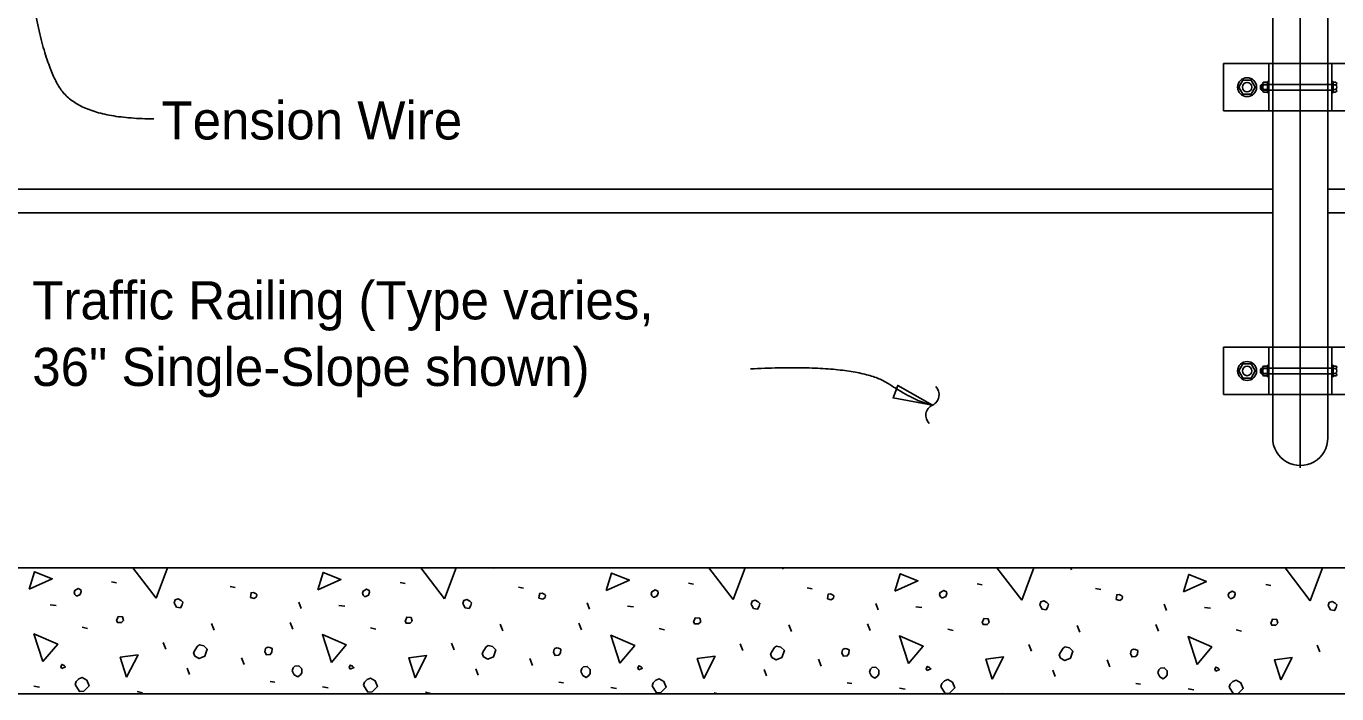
# Model space of a CAD drawing. Extents: x 0 to 41.2, y 0 to 26.
# Drawn here: x 5.48 to 12.4, y 13.47 to 17 of the extents above; entities that cross this region are included whole.
import ezdxf

# ---------------------------------------------------------------- set-up
doc = ezdxf.new("R2010")
doc.units = 0
for name, color, linetype in [('CL_Major', 7, 'Continuous'), ('Dimension', 7, 'Continuous'), ('Miscellaneous', 7, 'Continuous'), ('SteelMisc', 7, 'Continuous'), ('SteelMisc_h', 7, 'Continuous'), ('SupstrConc', 7, 'Continuous'), ('TextStructures', 7, 'Continuous')]:
    doc.layers.add(name, color=color, linetype=linetype)

msp = doc.modelspace()

# ---------------------------------------------------------------- linework, layer by layer
at = {"layer": 'CL_Major'}
msp.add_line((12.2062, 24.6326), (12.2062, 14.6639), dxfattribs=at)
at = {"layer": 'Dimension'}
msp.add_lwpolyline([(10.2634, 14.9952), (10.0798, 15.0997), (10.0556, 15.0334)], close=True, dxfattribs=at)
for centre, start, end in [((10.2392, 15.0503), 294.14658, 45.87379), ((10.2879, 14.9415), 114.14657, 225.87379)]:
    msp.add_arc(centre, 0.0596, start, end, dxfattribs=at)
for points in [[(6.1508, 16.5088), (5.753, 16.5088), (5.549, 16.8458), (5.4877, 17.3027)], [(9.3027, 15.1869), (9.8656, 15.2152), (10.187, 15.0071), (10.2636, 14.9959)]]:
    msp.add_open_spline(points, degree=2, dxfattribs=at)
at = {"layer": 'Miscellaneous'}
for p, q in [((11.9986, 16.6691), (11.9986, 16.6812)), ((12.0044, 16.6691), (12.0044, 16.6812)), ((11.9986, 15.1691), (11.9986, 15.1812)), ((12.0044, 15.1691), (12.0044, 15.1812)), ((7.9504, 14.1326), (7.9491, 14.1361)), ((9.4742, 14.129), (9.4716, 14.1361)), ((10.9981, 14.1255), (10.9942, 14.1361)), ((5.9281, 14.0619), (5.9546, 14.0566)), ((7.4519, 14.0583), (7.4784, 14.053)), ((8.9757, 14.0548), (9.0023, 14.0495)), ((10.4996, 14.0513), (10.5261, 14.046)), ((6.5539, 14.0371), (6.5804, 14.0318)), ((8.0777, 14.0336), (8.1042, 14.0283)), ((9.6015, 14.0301), (9.628, 14.0247)), ((11.1253, 14.0265), (11.1519, 14.0212)), ((12.0234, 14.0477), (12.0499, 14.0424)), ((5.6046, 13.9399), (5.6364, 13.9364)), ((6.9287, 13.9205), (6.9163, 13.954)), ((7.1284, 13.9364), (7.1602, 13.9328)), ((8.4525, 13.9169), (8.4401, 13.9505)), ((8.6522, 13.9328), (8.6841, 13.9293)), ((9.9763, 13.9134), (9.9639, 13.947)), ((10.1761, 13.9293), (10.2079, 13.9258)), ((11.5001, 13.9098), (11.4877, 13.9434)), ((11.6999, 13.9258), (11.7317, 13.9222)), ((6.8862, 13.8108), (6.8721, 13.8462)), ((5.7725, 13.8215), (5.8008, 13.8144)), ((6.4708, 13.8055), (6.4567, 13.8409)), ((7.2964, 13.8179), (7.3246, 13.8108)), ((7.9946, 13.802), (7.9805, 13.8374)), ((8.4101, 13.8073), (8.3959, 13.8427)), ((8.8202, 13.8144), (8.8485, 13.8073)), ((9.5184, 13.7985), (9.5043, 13.8338)), ((9.9339, 13.8038), (9.9197, 13.8391)), ((10.344, 13.8108), (10.3723, 13.8038)), ((11.0423, 13.7949), (11.0281, 13.8303)), ((11.4577, 13.8002), (11.4435, 13.8356)), ((11.8678, 13.8073), (11.8961, 13.8002)), ((6.2145, 13.7048), (6.2003, 13.7401)), ((7.7383, 13.7012), (7.7242, 13.7366)), ((9.2621, 13.6977), (9.248, 13.7331)), ((10.7859, 13.6942), (10.7718, 13.7295)), ((12.3097, 13.6906), (12.2956, 13.726)), ((6.6281, 13.6235), (6.614, 13.6588)), ((8.152, 13.6199), (8.1378, 13.6553)), ((9.6758, 13.6164), (9.6616, 13.6518)), ((11.1996, 13.6129), (11.1854, 13.6482)), ((6.34, 13.5722), (6.3276, 13.6058)), ((7.8638, 13.5687), (7.8514, 13.6023)), ((9.3876, 13.5651), (9.3753, 13.5987)), ((10.9114, 13.5616), (10.8991, 13.5952)), ((5.518, 13.5103), (5.548, 13.505)), ((6.766, 13.5351), (6.7908, 13.5315)), ((7.0418, 13.5068), (7.0719, 13.5015)), ((8.2898, 13.5315), (8.3146, 13.528)), ((8.5656, 13.5033), (8.5957, 13.498)), ((9.8137, 13.528), (9.8384, 13.5245)), ((10.0894, 13.4997), (10.1195, 13.4944)), ((11.3375, 13.5245), (11.3622, 13.5209)), ((6.0625, 13.482), (6.0907, 13.475)), ((7.5863, 13.4785), (7.6146, 13.4714)), ((9.1101, 13.475), (9.1322, 13.4695)), ((10.6339, 13.4714), (10.6418, 13.4695)), ((11.6132, 13.4962), (11.6433, 13.4909))]:
    msp.add_line(p, q, dxfattribs=at)
for points in [[(6.1632, 13.9753), (6.041, 14.1361)], [(6.2233, 14.1361), (6.1632, 13.9753)], [(7.687, 13.9717), (7.5621, 14.1361)], [(7.7485, 14.1361), (7.687, 13.9717)], [(9.2109, 13.9682), (9.0832, 14.1361)], [(9.2736, 14.1361), (9.2109, 13.9682)], [(10.7347, 13.9646), (10.6043, 14.1361)], [(10.7988, 14.1361), (10.7347, 13.9646)], [(12.2585, 13.9611), (12.1255, 14.1361)], [(12.3239, 14.1361), (12.2585, 13.9611)], [(5.4932, 14.023), (5.5215, 14.1149), (5.6152, 14.0778), (5.4932, 14.023)], [(7.0171, 14.0194), (7.0453, 14.1114), (7.139, 14.0742), (7.0171, 14.0194)], [(8.5409, 14.0159), (8.5692, 14.1078), (8.6628, 14.0707), (8.5409, 14.0159)], [(10.0647, 14.0124), (10.093, 14.1043), (10.1867, 14.0672), (10.0647, 14.0124)], [(11.5885, 14.0088), (11.6168, 14.1008), (11.7105, 14.0636), (11.5885, 14.0088)], [(5.7407, 13.9876), (5.7478, 13.9876), (5.7619, 13.9947), (5.7672, 14.0106), (5.7655, 14.0194), (5.7513, 14.0265), (5.7337, 14.0159), (5.7301, 14.0053), (5.7337, 13.9947), (5.7407, 13.9876)], [(6.6617, 13.9788), (6.6812, 13.9735), (6.6935, 13.9823), (6.6953, 13.9947), (6.6918, 13.9982), (6.6776, 14.0053), (6.6653, 14.0035), (6.6635, 13.9912), (6.6617, 13.9788)], [(7.2645, 13.9841), (7.2716, 13.9841), (7.2858, 13.9912), (7.2911, 14.0071), (7.2893, 14.0159), (7.2751, 14.023), (7.2575, 14.0124), (7.2539, 14.0018), (7.2575, 13.9912), (7.2645, 13.9841)], [(8.1855, 13.9753), (8.205, 13.9699), (8.2174, 13.9788), (8.2191, 13.9912), (8.2156, 13.9947), (8.2015, 14.0018), (8.1891, 14), (8.1873, 13.9876), (8.1855, 13.9753)], [(8.7884, 13.9806), (8.7954, 13.9806), (8.8096, 13.9876), (8.8149, 14.0035), (8.8131, 14.0124), (8.799, 14.0194), (8.7813, 14.0088), (8.7777, 13.9982), (8.7813, 13.9876), (8.7884, 13.9806)], [(9.7094, 13.9717), (9.7288, 13.9664), (9.7412, 13.9753), (9.7429, 13.9876), (9.7394, 13.9912), (9.7253, 13.9982), (9.7129, 13.9965), (9.7111, 13.9841), (9.7094, 13.9717)], [(10.3122, 13.977), (10.3192, 13.977), (10.3334, 13.9841), (10.3387, 14), (10.3369, 14.0088), (10.3228, 14.0159), (10.3051, 14.0053), (10.3016, 13.9947), (10.3051, 13.9841), (10.3122, 13.977)], [(11.2332, 13.9682), (11.2526, 13.9629), (11.265, 13.9717), (11.2668, 13.9841), (11.2632, 13.9876), (11.2491, 13.9947), (11.2367, 13.9929), (11.2349, 13.9806), (11.2332, 13.9682)], [(11.836, 13.9735), (11.8431, 13.9735), (11.8572, 13.9806), (11.8625, 13.9965), (11.8607, 14.0053), (11.8466, 14.0124), (11.8289, 14.0018), (11.8254, 13.9912), (11.8289, 13.9806), (11.836, 13.9735)], [(6.2622, 13.9434), (6.2711, 13.9275), (6.2923, 13.924), (6.3011, 13.9399), (6.3046, 13.954), (6.2958, 13.9629), (6.2799, 13.9717), (6.264, 13.9664), (6.2587, 13.9505), (6.2622, 13.9434)], [(7.786, 13.9399), (7.7949, 13.924), (7.8161, 13.9205), (7.8249, 13.9364), (7.8285, 13.9505), (7.8196, 13.9593), (7.8037, 13.9682), (7.7878, 13.9629), (7.7825, 13.947), (7.786, 13.9399)], [(9.3098, 13.9364), (9.3187, 13.9205), (9.3399, 13.9169), (9.3487, 13.9328), (9.3523, 13.947), (9.3434, 13.9558), (9.3275, 13.9646), (9.3116, 13.9593), (9.3063, 13.9434), (9.3098, 13.9364)], [(10.8337, 13.9328), (10.8425, 13.9169), (10.8637, 13.9134), (10.8726, 13.9293), (10.8761, 13.9434), (10.8672, 13.9523), (10.8513, 13.9611), (10.8354, 13.9558), (10.8301, 13.9399), (10.8337, 13.9328)], [(12.3575, 13.9293), (12.3663, 13.9134), (12.3875, 13.9098), (12.3964, 13.9258), (12.3999, 13.9399), (12.3911, 13.9487), (12.3752, 13.9576), (12.3592, 13.9523), (12.3539, 13.9364), (12.3575, 13.9293)], [(5.9599, 13.8462), (5.9811, 13.8462), (5.9917, 13.8568), (5.9864, 13.8763), (5.9635, 13.878), (5.9599, 13.8674), (5.9546, 13.8586), (5.9599, 13.8462), (5.9564, 13.8497)], [(7.4837, 13.8427), (7.505, 13.8427), (7.5156, 13.8533), (7.5103, 13.8727), (7.4873, 13.8745), (7.4837, 13.8639), (7.4784, 13.855), (7.4837, 13.8427), (7.4802, 13.8462)], [(9.0076, 13.8391), (9.0288, 13.8391), (9.0394, 13.8497), (9.0341, 13.8692), (9.0111, 13.871), (9.0076, 13.8603), (9.0023, 13.8515), (9.0076, 13.8391), (9.004, 13.8427)], [(10.5314, 13.8356), (10.5526, 13.8356), (10.5632, 13.8462), (10.5579, 13.8657), (10.5349, 13.8674), (10.5314, 13.8568), (10.5261, 13.848), (10.5314, 13.8356), (10.5278, 13.8391)], [(12.0552, 13.8321), (12.0764, 13.8321), (12.087, 13.8427), (12.0817, 13.8621), (12.0587, 13.8639), (12.0552, 13.8533), (12.0499, 13.8444), (12.0552, 13.8321), (12.0517, 13.8356)], [(5.5657, 13.6394), (5.518, 13.7861), (5.6435, 13.7313), (5.5657, 13.6394)], [(7.0895, 13.6358), (7.0418, 13.7826), (7.1673, 13.7278), (7.0895, 13.6358)], [(8.6133, 13.6323), (8.5656, 13.779), (8.6911, 13.7242), (8.6133, 13.6323)], [(10.1372, 13.6288), (10.0894, 13.7755), (10.2149, 13.7207), (10.1372, 13.6288)], [(6.3683, 13.6677), (6.3913, 13.6553), (6.4213, 13.6677), (6.4337, 13.7048), (6.416, 13.7225), (6.393, 13.7278), (6.3824, 13.7207), (6.37, 13.7012), (6.3612, 13.6853), (6.3683, 13.6677)], [(6.7377, 13.6906), (6.7466, 13.6747), (6.766, 13.6765), (6.7749, 13.6889), (6.7766, 13.7083), (6.7643, 13.7136), (6.7554, 13.7154), (6.7448, 13.7119), (6.7413, 13.7083), (6.7377, 13.6906)], [(7.8921, 13.6641), (7.9151, 13.6518), (7.9451, 13.6641), (7.9575, 13.7012), (7.9398, 13.7189), (7.9168, 13.7242), (7.9062, 13.7172), (7.8939, 13.6977), (7.885, 13.6818), (7.8921, 13.6641)], [(8.2616, 13.6871), (8.2704, 13.6712), (8.2898, 13.673), (8.2987, 13.6853), (8.3005, 13.7048), (8.2881, 13.7101), (8.2792, 13.7119), (8.2686, 13.7083), (8.2651, 13.7048), (8.2616, 13.6871)], [(9.4159, 13.6606), (9.4389, 13.6482), (9.4689, 13.6606), (9.4813, 13.6977), (9.4636, 13.7154), (9.4407, 13.7207), (9.4301, 13.7136), (9.4177, 13.6942), (9.4088, 13.6783), (9.4159, 13.6606)], [(9.7854, 13.6836), (9.7942, 13.6677), (9.8137, 13.6694), (9.8225, 13.6818), (9.8243, 13.7012), (9.8119, 13.7066), (9.8031, 13.7083), (9.7924, 13.7048), (9.7889, 13.7012), (9.7854, 13.6836)], [(10.9397, 13.6571), (10.9627, 13.6447), (10.9928, 13.6571), (11.0051, 13.6942), (10.9875, 13.7119), (10.9645, 13.7172), (10.9539, 13.7101), (10.9415, 13.6906), (10.9327, 13.6747), (10.9397, 13.6571)], [(11.3092, 13.68), (11.318, 13.6641), (11.3375, 13.6659), (11.3463, 13.6783), (11.3481, 13.6977), (11.3357, 13.703), (11.3269, 13.7048), (11.3163, 13.7012), (11.3127, 13.6977), (11.3092, 13.68)], [(11.661, 13.6252), (11.6132, 13.772), (11.7388, 13.7172), (11.661, 13.6252)], [(6.0077, 13.5581), (5.9741, 13.6624), (6.0678, 13.6747), (6.0077, 13.5581)], [(7.5315, 13.5545), (7.4979, 13.6588), (7.5916, 13.6712), (7.5315, 13.5545)], [(9.0553, 13.551), (9.0217, 13.6553), (9.1154, 13.6677), (9.0553, 13.551)], [(10.5791, 13.5475), (10.5455, 13.6518), (10.6392, 13.6641), (10.5791, 13.5475)], [(12.1029, 13.5439), (12.0693, 13.6482), (12.163, 13.6606), (12.1029, 13.5439)], [(5.6647, 13.604), (5.6842, 13.6129), (5.6771, 13.6199), (5.6647, 13.6252), (5.6594, 13.6129), (5.6647, 13.604)], [(6.8827, 13.5916), (6.8933, 13.5704), (6.911, 13.5598), (6.9251, 13.5704), (6.9322, 13.581), (6.9322, 13.6023), (6.9163, 13.6182), (6.8968, 13.6164), (6.888, 13.6076), (6.8827, 13.5916)], [(7.1885, 13.6005), (7.208, 13.6093), (7.2009, 13.6164), (7.1885, 13.6217), (7.1832, 13.6093), (7.1885, 13.6005)], [(8.4065, 13.5881), (8.4171, 13.5669), (8.4348, 13.5563), (8.4489, 13.5669), (8.456, 13.5775), (8.456, 13.5987), (8.4401, 13.6146), (8.4207, 13.6129), (8.4118, 13.604), (8.4065, 13.5881)], [(8.7123, 13.5969), (8.7318, 13.6058), (8.7247, 13.6129), (8.7123, 13.6182), (8.707, 13.6058), (8.7123, 13.5969)], [(9.9303, 13.5846), (9.9409, 13.5634), (9.9586, 13.5528), (9.9728, 13.5634), (9.9798, 13.574), (9.9798, 13.5952), (9.9639, 13.6111), (9.9445, 13.6093), (9.9356, 13.6005), (9.9303, 13.5846)], [(10.2362, 13.5934), (10.2556, 13.6023), (10.2485, 13.6093), (10.2362, 13.6146), (10.2309, 13.6023), (10.2362, 13.5934)], [(11.4541, 13.581), (11.4648, 13.5598), (11.4824, 13.5492), (11.4966, 13.5598), (11.5036, 13.5704), (11.5036, 13.5916), (11.4877, 13.6076), (11.4683, 13.6058), (11.4594, 13.5969), (11.4541, 13.581)], [(11.76, 13.5899), (11.7794, 13.5987), (11.7723, 13.6058), (11.76, 13.6111), (11.7547, 13.5987), (11.76, 13.5899)], [(5.7354, 13.5192), (5.7584, 13.482), (5.7814, 13.4838), (5.7902, 13.4927), (5.8097, 13.5121), (5.7973, 13.5421), (5.7725, 13.5563), (5.7549, 13.5492), (5.7407, 13.5351), (5.7354, 13.5192)], [(7.2592, 13.5156), (7.2822, 13.4785), (7.3052, 13.4803), (7.314, 13.4891), (7.3335, 13.5086), (7.3211, 13.5386), (7.2964, 13.5528), (7.2787, 13.5457), (7.2645, 13.5315), (7.2592, 13.5156)], [(8.7831, 13.5121), (8.806, 13.475), (8.829, 13.4767), (8.8379, 13.4856), (8.8573, 13.505), (8.8449, 13.5351), (8.8202, 13.5492), (8.8025, 13.5421), (8.7884, 13.528), (8.7831, 13.5121)], [(10.3069, 13.5086), (10.3298, 13.4714), (10.3528, 13.4732), (10.3617, 13.482), (10.3811, 13.5015), (10.3687, 13.5315), (10.344, 13.5457), (10.3263, 13.5386), (10.3122, 13.5245), (10.3069, 13.5086)], [(11.8738, 13.4695), (11.8766, 13.4697), (11.8855, 13.4785), (11.9049, 13.498), (11.8926, 13.528), (11.8678, 13.5421), (11.8501, 13.5351), (11.836, 13.5209), (11.8307, 13.505)], [(11.8307, 13.505), (11.8527, 13.4695)], [(6.5568, 13.4695), (6.5557, 13.4697), (6.5541, 13.4695)]]:
    msp.add_lwpolyline(points, dxfattribs=at)
at = {"layer": 'SteelMisc'}
for p, q in [((12.0604, 16.801), (12.0604, 17.2769)), ((12.3521, 16.801), (12.3521, 17.2769)), ((11.8002, 16.801), (12.6122, 16.801)), ((11.8002, 16.551), (11.8002, 16.801)), ((12.0396, 16.801), (12.0396, 16.551)), ((12.3729, 16.801), (12.3729, 16.551)), ((11.9958, 16.684), (12.0015, 16.6906)), ((11.9958, 16.6663), (11.9958, 16.684)), ((12.0015, 16.6906), (12.008, 16.6906)), ((12.0015, 16.6607), (12.0015, 16.6906)), ((12.008, 16.6939), (12.008, 16.6582)), ((12.0127, 16.689), (12.033, 16.689)), ((12.0129, 16.702), (12.033, 16.702)), ((12.033, 16.7063), (12.033, 16.6457)), ((12.033, 16.7063), (12.0396, 16.7063)), ((12.033, 16.702), (12.033, 16.65)), ((12.3792, 16.7063), (12.3731, 16.7063)), ((12.3939, 16.702), (12.3791, 16.702)), ((12.394, 16.689), (12.3791, 16.689)), ((12.3792, 16.7063), (12.3792, 16.6457)), ((11.9958, 16.6663), (12.0015, 16.6607)), ((12.0015, 16.6607), (12.008, 16.6607)), ((12.0127, 16.6631), (12.033, 16.6631)), ((12.013, 16.65), (12.033, 16.65)), ((12.033, 16.6457), (12.0396, 16.6457)), ((12.3792, 16.6457), (12.3731, 16.6457)), ((12.394, 16.663), (12.3791, 16.663)), ((12.3939, 16.65), (12.3791, 16.65)), ((12.6122, 16.551), (11.8002, 16.551)), ((12.0604, 16.551), (12.0604, 15.301)), ((12.3521, 16.551), (12.3521, 15.301)), ((11.8002, 15.301), (12.6122, 15.301)), ((11.8002, 15.051), (11.8002, 15.301)), ((12.0396, 15.301), (12.0396, 15.051)), ((12.3729, 15.301), (12.3729, 15.051)), ((11.9958, 15.184), (12.0015, 15.1906)), ((11.9958, 15.1663), (11.9958, 15.184)), ((11.9958, 15.1663), (12.0015, 15.1607)), ((12.0015, 15.1906), (12.008, 15.1906)), ((12.0015, 15.1607), (12.0015, 15.1906)), ((12.0015, 15.1607), (12.008, 15.1607)), ((12.008, 15.1939), (12.008, 15.1582)), ((12.0127, 15.189), (12.033, 15.189)), ((12.0127, 15.1631), (12.033, 15.1631)), ((12.0129, 15.202), (12.033, 15.202)), ((12.033, 15.2063), (12.033, 15.1457)), ((12.033, 15.2063), (12.0396, 15.2063)), ((12.033, 15.202), (12.033, 15.15)), ((12.3792, 15.2063), (12.3731, 15.2063)), ((12.3939, 15.202), (12.3791, 15.202)), ((12.394, 15.189), (12.3791, 15.189)), ((12.394, 15.163), (12.3791, 15.163)), ((12.3792, 15.2063), (12.3792, 15.1457)), ((12.013, 15.15), (12.033, 15.15)), ((12.033, 15.1457), (12.0396, 15.1457)), ((12.3792, 15.1457), (12.3731, 15.1457)), ((12.3939, 15.15), (12.3791, 15.15)), ((12.6122, 15.051), (11.8002, 15.051)), ((12.0603, 15.051), (12.0603, 14.8218)), ((12.3519, 14.8218), (12.3519, 15.051))]:
    msp.add_line(p, q, dxfattribs=at)
for points in [[(11.9036, 16.7135), (11.9469, 16.7135), (11.9686, 16.676), (11.9469, 16.6385), (11.9036, 16.6385), (11.8819, 16.676)], [(11.9036, 15.2135), (11.9469, 15.2135), (11.9686, 15.176), (11.9469, 15.1385), (11.9036, 15.1385), (11.8819, 15.176)]]:
    msp.add_lwpolyline(points, close=True, dxfattribs=at)
for centre, radius in [((11.9252, 16.676), 0.05), ((11.9252, 16.676), 0.025), ((11.9252, 15.176), 0.05), ((11.9252, 15.176), 0.025)]:
    msp.add_circle(centre, radius, dxfattribs=at)
for centre, radius, start, end in [((12.0145, 16.6955), 0.00674, 104.48908, 254.18889), ((12.0274, 16.676), 0.0196, 138.62797, 221.37203), ((12.3922, 16.6955), 0.00673, 285.7823, 75.54039), ((12.3793, 16.676), 0.0196, 318.62797, 41.37203), ((12.0145, 16.6565), 0.00673, 105.7823, 255.54039), ((12.3922, 16.6565), 0.00674, 284.48908, 74.18889), ((12.0145, 15.1955), 0.00674, 104.48908, 254.18889), ((12.0274, 15.176), 0.0196, 138.62797, 221.37203), ((12.0145, 15.1565), 0.00673, 105.7823, 255.54039), ((12.3922, 15.1955), 0.00673, 285.7823, 75.54039), ((12.3922, 15.1565), 0.00674, 284.48908, 74.18889), ((12.3793, 15.176), 0.0196, 318.62797, 41.37203)]:
    msp.add_arc(centre, radius, start, end, dxfattribs=at)
msp.add_ellipse((12.2062, 14.8218), major_axis=(0, 0.1458), ratio=0.999499, start_param=1.570796, end_param=4.712389, dxfattribs=at)
at = {"layer": 'SteelMisc_h'}
for p, q in [((12.0604, 16.801), (12.0604, 16.551)), ((12.3521, 16.801), (12.3521, 16.551)), ((12.3729, 16.6906), (12.008, 16.6906)), ((12.008, 16.6607), (12.3729, 16.6607)), ((12.0604, 15.301), (12.0604, 15.051)), ((12.3521, 15.301), (12.3521, 15.051)), ((12.3729, 15.1906), (12.008, 15.1906)), ((12.008, 15.1607), (12.3729, 15.1607))]:
    msp.add_line(p, q, dxfattribs=at)
at = {"layer": 'SupstrConc'}
for p, q in [((2.352, 16.1361), (12.0604, 16.1361)), ((12.3521, 16.1361), (22.0604, 16.1361)), ((2.352, 16.0111), (12.0604, 16.0111)), ((12.3521, 16.0111), (22.0604, 16.0111)), ((0.8193, 14.1361), (23.5931, 14.1361)), ((0.8193, 13.4695), (23.5931, 13.4695))]:
    msp.add_line(p, q, dxfattribs=at)

# ---------------------------------------------------------------- texts
at = {"layer": 'Dimension'}
for s, p in [('Traffic Railing (Type varies,', (5.5094, 15.4486)), ('36" Single-Slope shown)', (5.5094, 15.0966))]:
    msp.add_text(s, height=0.2016, dxfattribs=at).set_placement(p)
at = {"layer": 'TextStructures'}
msp.add_text('Tension Wire', height=0.2016, dxfattribs=at).set_placement((6.1918, 16.3995))

doc.saveas('drawing.dxf')
